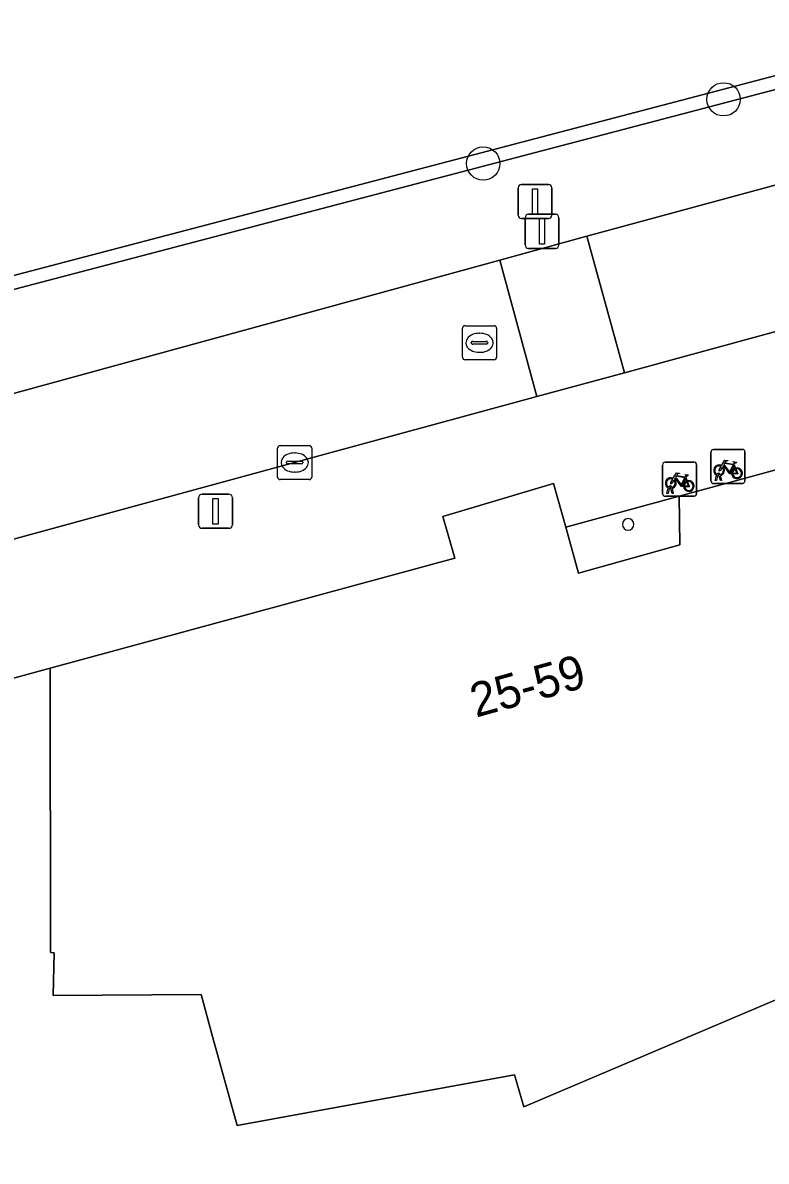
# Model space of a CAD drawing. Extents: x 159053 to 160042, y 380449 to 381423.
# Drawn here: x 159364.14 to 159385.97, y 380824.74 to 380858.17 of the extents above; entities that cross this region are included whole.
import ezdxf

# ---------------------------------------------------------------- set-up
doc = ezdxf.new("R2010")
doc.units = 0
for name, color, linetype in [('IMGEO_Afsluitpaal', 7, 'Continuous'), ('IMGEO_Boom', 7, 'Continuous'), ('IMGEO_Erf', 7, 'Continuous'), ('IMGEO_Fietsenrek', 7, 'Continuous'), ('IMGEO_Groenvoorziening', 7, 'Continuous'), ('IMGEO_Haag', 7, 'Continuous'), ('IMGEO_Kolk', 7, 'Continuous'), ('IMGEO_Lichtmast', 7, 'Continuous'), ('IMGEO_Pand', 7, 'Continuous'), ('IMGEO_Pand_nummerreeks', 7, 'Continuous'), ('IMGEO_Rijbaan_lokaal_open', 7, 'Continuous'), ('IMGEO_Rioolput', 7, 'Continuous'), ('IMGEO_Voetpad_open', 7, 'Continuous')]:
    doc.layers.add(name, color=color, linetype=linetype)

msp = doc.modelspace()

# ---------------------------------------------------------------- linework, layer by layer
at = {"layer": 'IMGEO_Afsluitpaal'}
for p, q in [((159378.684, 380852.517), (159378.684, 380853.317)), ((159378.684, 380853.317), (159378.684, 380852.517)), ((159378.784, 380853.417), (159379.574, 380853.417)), ((159379.574, 380853.417), (159378.784, 380853.417)), ((159379.674, 380853.317), (159379.674, 380852.517)), ((159379.674, 380852.517), (159379.674, 380853.317)), ((159379.574, 380852.417), (159378.784, 380852.417)), ((159378.784, 380852.417), (159379.574, 380852.417)), ((159378.886, 380851.643), (159378.886, 380852.443)), ((159378.886, 380852.443), (159378.886, 380851.643)), ((159378.986, 380852.543), (159379.776, 380852.543)), ((159379.776, 380852.543), (159378.986, 380852.543)), ((159379.876, 380852.443), (159379.876, 380851.643)), ((159379.876, 380851.643), (159379.876, 380852.443)), ((159379.776, 380851.543), (159378.986, 380851.543)), ((159378.986, 380851.543), (159379.776, 380851.543))]:
    msp.add_line(p, q, dxfattribs=at)
for points in [[(159379.104, 380853.292), (159379.254, 380853.292), (159379.254, 380852.542), (159379.104, 380852.542), (159379.104, 380853.292)], [(159379.306, 380852.418), (159379.456, 380852.418), (159379.456, 380851.668), (159379.306, 380851.668), (159379.306, 380852.418)]]:
    msp.add_lwpolyline(points, dxfattribs=at)
for centre, start, end in [((159378.784, 380853.317), 90, 180), ((159378.784, 380853.317), 90, 180), ((159379.574, 380853.317), 0, 90), ((159379.574, 380853.317), 360, 90), ((159378.784, 380852.517), 180, 270), ((159378.784, 380852.517), 180, 270), ((159378.986, 380852.443), 90, 180), ((159378.986, 380852.443), 90, 180), ((159379.574, 380852.517), 270, 0), ((159379.574, 380852.517), 270, 0), ((159379.776, 380852.443), 0, 90), ((159379.776, 380852.443), 360, 90), ((159378.986, 380851.643), 180, 270), ((159378.986, 380851.643), 180, 270), ((159379.776, 380851.643), 270, 0), ((159379.776, 380851.643), 270, 0)]:
    msp.add_arc(centre, 0.1, start, end, dxfattribs=at)
at = {"layer": 'IMGEO_Boom'}
for centre in [(159384.716, 380855.918), (159377.659, 380854.033)]:
    msp.add_circle(centre, 0.489, dxfattribs=at)
at = {"layer": 'IMGEO_Erf'}
msp.add_lwpolyline([(159389.815, 380824.538), (159402.333, 380832.35), (159393.73, 380847.1), (159391.961, 380846.597), (159396.172, 380839.392), (159396.866, 380838.211), (159393.026, 380835.951), (159393.845, 380832.956), (159388.154, 380828.951), (159387.813, 380830.148), (159378.848, 380826.342), (159378.573, 380827.282), (159370.429, 380825.789), (159369.712, 380828.402), (159369.374, 380829.635), (159365.031, 380829.603), (159365.059, 380830.863), (159364.954, 380830.868), (159364.937, 380839.219), (159363.135, 380838.73)], dxfattribs=at)
msp.add_lwpolyline([(159380.08, 380843.353), (159380.457, 380842.006), (159383.434, 380842.835), (159383.414, 380844.263)], close=True, dxfattribs=at)
for start, end in [(0, 180), (180, 0)]:
    msp.add_arc((159381.914, 380843.44), 0.17, start, end, dxfattribs=at)
at = {"layer": 'IMGEO_Fietsenrek'}
for p, q in [((159384.417, 380845.639), (159385.258, 380845.639)), ((159385.258, 380845.639), (159384.417, 380845.639)), ((159382.999, 380845.265), (159383.84, 380845.265)), ((159383.84, 380845.265), (159382.999, 380845.265)), ((159384.342, 380844.714), (159384.342, 380845.555)), ((159384.342, 380845.555), (159384.342, 380844.714)), ((159385.342, 380845.564), (159385.342, 380844.723)), ((159385.342, 380844.723), (159385.342, 380845.564)), ((159382.924, 380844.34), (159382.924, 380845.181)), ((159382.924, 380845.181), (159382.924, 380844.34)), ((159383.924, 380845.19), (159383.924, 380844.349)), ((159383.924, 380844.349), (159383.924, 380845.19)), ((159385.029, 380845.188), (159385.065, 380845.093)), ((159383.611, 380844.814), (159383.647, 380844.719)), ((159385.267, 380844.639), (159384.426, 380844.639)), ((159384.426, 380844.639), (159385.267, 380844.639)), ((159384.469, 380844.723), (159384.508, 380844.883)), ((159384.503, 380844.723), (159384.469, 380844.723)), ((159384.538, 380844.871), (159384.503, 380844.723)), ((159384.58, 380844.895), (159384.579, 380844.899)), ((159384.621, 380844.723), (159384.587, 380844.865)), ((159384.611, 380844.906), (159384.612, 380844.899)), ((159384.619, 380844.869), (159384.654, 380844.723)), ((159384.654, 380844.723), (159384.621, 380844.723)), ((159383.849, 380844.265), (159383.008, 380844.265)), ((159383.008, 380844.265), (159383.849, 380844.265)), ((159383.051, 380844.349), (159383.09, 380844.509)), ((159383.085, 380844.349), (159383.051, 380844.349)), ((159383.12, 380844.497), (159383.085, 380844.349)), ((159383.162, 380844.521), (159383.161, 380844.525)), ((159383.203, 380844.349), (159383.169, 380844.491)), ((159383.193, 380844.532), (159383.194, 380844.525)), ((159383.201, 380844.495), (159383.236, 380844.349)), ((159383.236, 380844.349), (159383.203, 380844.349))]:
    msp.add_line(p, q, dxfattribs=at)
for points in [[(159384.655, 380845.165), (159384.75, 380845.329), (159384.836, 380845.315), (159384.838, 380845.306), (159384.782, 380845.295), (159384.755, 380845.25), (159385.011, 380845.209)], [(159385.011, 380845.209), (159385.036, 380845.258), (159385.03, 380845.262), (159385.007, 380845.266), (159384.995, 380845.273), (159384.994, 380845.276), (159384.996, 380845.281), (159385.091, 380845.266), (159385.093, 380845.256), (159385.083, 380845.243), (159385.071, 380845.237), (159385.057, 380845.243), (159385.029, 380845.188)], [(159383.237, 380844.791), (159383.332, 380844.955), (159383.418, 380844.941), (159383.42, 380844.932), (159383.364, 380844.921), (159383.337, 380844.876), (159383.593, 380844.835)], [(159384.676, 380845.113), (159384.624, 380845.023), (159384.584, 380844.998), (159384.585, 380845.045), (159384.64, 380845.139)], [(159384.951, 380844.921), (159384.901, 380844.921), (159384.71, 380845.172), (159384.691, 380845.14)], [(159384.998, 380845.184), (159384.741, 380845.225), (159384.724, 380845.196), (159384.891, 380844.976), (159384.998, 380845.184)], [(159385.046, 380845.086), (159385.016, 380845.163), (159384.907, 380844.945), (159384.95, 380844.945)], [(159384.98, 380844.945), (159385.1, 380844.944), (159385.056, 380845.058)], [(159385.076, 380845.065), (159385.131, 380844.92), (159384.981, 380844.92)], [(159383.258, 380844.739), (159383.206, 380844.649), (159383.166, 380844.624), (159383.167, 380844.671), (159383.222, 380844.765)], [(159383.533, 380844.547), (159383.483, 380844.547), (159383.292, 380844.798), (159383.273, 380844.766)], [(159383.58, 380844.81), (159383.323, 380844.851), (159383.306, 380844.822), (159383.473, 380844.602), (159383.58, 380844.81)], [(159383.628, 380844.712), (159383.598, 380844.789), (159383.489, 380844.571), (159383.532, 380844.571)], [(159383.562, 380844.571), (159383.682, 380844.57), (159383.638, 380844.684)], [(159383.658, 380844.691), (159383.713, 380844.546), (159383.563, 380844.546)], [(159383.593, 380844.835), (159383.618, 380844.884), (159383.612, 380844.888), (159383.589, 380844.892), (159383.577, 380844.899), (159383.576, 380844.902), (159383.578, 380844.907), (159383.673, 380844.892), (159383.675, 380844.882), (159383.665, 380844.869), (159383.653, 380844.863), (159383.639, 380844.869), (159383.611, 380844.814)]]:
    msp.add_lwpolyline(points, dxfattribs=at)
for centre, radius, start, end in [((159384.42, 380845.561), 0.0779, 92.4484, 184.2845), ((159384.42, 380845.561), 0.0779, 92.4484, 184.2845), ((159385.264, 380845.561), 0.0779, 2.4484, 94.2845), ((159385.264, 380845.561), 0.0779, 2.4484, 94.2845), ((159383.002, 380845.187), 0.0779, 92.4484, 184.2845), ((159383.002, 380845.187), 0.0779, 92.4484, 184.2845), ((159383.846, 380845.187), 0.0779, 2.4484, 94.2845), ((159383.846, 380845.187), 0.0779, 2.4484, 94.2845), ((159384.582, 380845.024), 0.159, 62.6766, 242.1369), ((159384.582, 380845.024), 0.129, 63.3192, 238.903), ((159384.562, 380844.895), 0.0499, 12.8025, 158.6934), ((159384.582, 380845.024), 0.129, 283.6043, 43.4302), ((159384.582, 380845.024), 0.159, 283.5766, 46.6042), ((159385.109, 380844.94), 0.159, 113.3408, 178.3217), ((159385.109, 380844.94), 0.159, 187.0065, 105.7708), ((159385.109, 380844.94), 0.129, 113.923, 177.9556), ((159385.109, 380844.94), 0.129, 188.6715, 104.5883), ((159383.164, 380844.65), 0.159, 62.6766, 242.1369), ((159383.164, 380844.65), 0.129, 63.3192, 238.903), ((159383.164, 380844.65), 0.129, 283.6043, 43.4302), ((159383.164, 380844.65), 0.159, 283.5766, 46.6042), ((159383.691, 380844.566), 0.159, 113.3408, 178.3217), ((159383.691, 380844.566), 0.159, 187.0065, 105.7708), ((159383.691, 380844.566), 0.129, 113.923, 177.9556), ((159383.691, 380844.566), 0.129, 188.6715, 104.5883), ((159384.42, 380844.717), 0.0779, 182.4484, 274.2845), ((159384.42, 380844.717), 0.0779, 182.4484, 274.2845), ((159384.582, 380845.024), 0.159, 253.9967, 271.7867), ((159384.562, 380844.895), 0.0174, 12.8025, 163.4502), ((159384.582, 380845.024), 0.129, 253.415, 269.0204), ((159385.264, 380844.717), 0.0779, 272.4484, 4.2845), ((159385.264, 380844.717), 0.0779, 272.4484, 4.2845), ((159383.002, 380844.343), 0.0779, 182.4484, 274.2845), ((159383.002, 380844.343), 0.0779, 182.4484, 274.2845), ((159383.144, 380844.521), 0.0499, 12.8025, 158.6934), ((159383.164, 380844.65), 0.159, 253.9967, 271.7867), ((159383.144, 380844.521), 0.0174, 12.8025, 163.4502), ((159383.164, 380844.65), 0.129, 253.415, 269.0204), ((159383.846, 380844.343), 0.0779, 272.4484, 4.2845), ((159383.846, 380844.343), 0.0779, 272.4484, 4.2845)]:
    msp.add_arc(centre, radius, start, end, dxfattribs=at)
at = {"layer": 'IMGEO_Groenvoorziening'}
for points in [[(159339.63, 380858.444), (159343.386, 380845.223), (159357.481, 380849.075), (159416.608, 380864.597), (159415.898, 380867.448), (159412.172, 380882.306), (159399.303, 380929.877)], [(159378.145, 380851.195), (159380.699, 380851.901), (159412.443, 380860.514), (159415.366, 380861.29), (159417.874, 380861.883), (159417.452, 380863.784), (159416.656, 380864.403), (159416.707, 380864.21), (159357.585, 380848.689), (159343.492, 380844.837), (159340.652, 380844.061), (159220.908, 380811.334), (159220.855, 380811.527), (159220.802, 380811.72), (159194.979, 380906.143), (159194.248, 380908.271), (159191.665, 380904.574), (159202.148, 380866.415), (159202.911, 380863.663), (159207.936, 380845.286), (159216.661, 380813.316)], [(159224.154, 380809.069), (159238.334, 380812.95), (159237.679, 380815.383), (159241.802, 380816.509), (159242.456, 380814.078), (159262.189, 380819.479), (159264.76, 380820.184), (159291.981, 380827.607), (159291.367, 380829.924), (159295.75, 380831.125), (159296.393, 380828.81), (159310.422, 380832.636), (159318.548, 380834.869), (159321.098, 380835.572), (159350.091, 380843.512), (159349.447, 380845.979), (159353.576, 380847.071), (159354.213, 380844.641), (159378.145, 380851.195)]]:
    msp.add_lwpolyline(points, dxfattribs=at)
msp.add_lwpolyline([(159416.656, 380864.403), (159416.608, 380864.597), (159357.481, 380849.075), (159343.386, 380845.223), (159340.546, 380844.447), (159220.802, 380811.72), (159220.855, 380811.527), (159220.908, 380811.334), (159340.652, 380844.061), (159343.492, 380844.837), (159357.585, 380848.689), (159416.707, 380864.21)], close=True, dxfattribs=at)
at = {"layer": 'IMGEO_Haag'}
msp.add_lwpolyline([(159416.656, 380864.403), (159416.608, 380864.597), (159357.481, 380849.075), (159343.386, 380845.223), (159340.546, 380844.447), (159220.802, 380811.72), (159220.855, 380811.527), (159220.908, 380811.334), (159340.652, 380844.061), (159343.492, 380844.837), (159357.585, 380848.689), (159416.707, 380864.21)], close=True, dxfattribs=at)
at = {"layer": 'IMGEO_Kolk'}
for p, q in [((159371.62, 380844.829), (159371.62, 380845.681)), ((159371.695, 380845.755), (159372.547, 380845.755)), ((159372.621, 380845.681), (159372.621, 380844.829)), ((159371.879, 380845.249), (159371.879, 380845.261)), ((159371.922, 380845.298), (159372.32, 380845.298)), ((159372.108, 380845.535), (159372.133, 380845.535)), ((159372.363, 380845.261), (159372.363, 380845.249)), ((159372.317, 380845.212), (159371.919, 380845.212)), ((159372.131, 380844.975), (159372.106, 380844.975)), ((159372.547, 380844.755), (159371.695, 380844.755))]:
    msp.add_line(p, q, dxfattribs=at)
for points in [[(159371.62, 380844.829), (159371.62, 380845.681)], [(159371.695, 380845.755), (159372.547, 380845.755)], [(159372.621, 380845.681), (159372.621, 380844.829)], [(159372.547, 380844.755), (159371.695, 380844.755)]]:
    msp.add_lwpolyline(points, dxfattribs=at)
for centre, radius, start, end in [((159371.697, 380845.679), 0.0765, 91.552, 178.448), ((159371.697, 380845.679), 0.0765, 91.552, 178.448), ((159372.545, 380845.679), 0.0765, 1.552, 88.448), ((159372.545, 380845.679), 0.0765, 1.552, 88.448), ((159371.919, 380845.258), 0.0403, 85.8775, 175.7526), ((159372.324, 380845.26), 0.0386, 1.7309, 96.639), ((159371.916, 380845.248), 0.0366, 178.938, 274.7102), ((159372.32, 380845.255), 0.043, 264.8664, 352.4533), ((159371.697, 380844.831), 0.0765, 181.552, 268.448), ((159371.697, 380844.831), 0.0765, 181.552, 268.448), ((159372.545, 380844.831), 0.0765, 271.552, 358.448), ((159372.545, 380844.831), 0.0765, 271.552, 358.448)]:
    msp.add_arc(centre, radius, start, end, dxfattribs=at)
for centre, major_axis, ratio, start_param, end_param in [((159372.107, 380845.255), (-0.387, 0.002), 0.722429, 4.712389, 7.853982), ((159372.132, 380845.255), (-0.39, 0.002), 0.717154, 1.570796, 4.712389)]:
    msp.add_ellipse(centre, major_axis=major_axis, ratio=ratio, start_param=start_param, end_param=end_param, dxfattribs=at)
at = {"layer": 'IMGEO_Lichtmast'}
for p, q in [((159369.4, 380844.323), (159370.19, 380844.323)), ((159370.19, 380844.323), (159369.4, 380844.323)), ((159369.3, 380843.423), (159369.3, 380844.223)), ((159369.3, 380844.223), (159369.3, 380843.423)), ((159370.29, 380844.223), (159370.29, 380843.423)), ((159370.29, 380843.423), (159370.29, 380844.223)), ((159370.19, 380843.323), (159369.4, 380843.323)), ((159369.4, 380843.323), (159370.19, 380843.323))]:
    msp.add_line(p, q, dxfattribs=at)
msp.add_lwpolyline([(159369.72, 380844.198), (159369.87, 380844.198), (159369.87, 380843.448), (159369.72, 380843.448), (159369.72, 380844.198)], dxfattribs=at)
for centre, start, end in [((159369.4, 380844.223), 90, 180), ((159369.4, 380844.223), 90, 180), ((159370.19, 380844.223), 0, 90), ((159370.19, 380844.223), 360, 90), ((159369.4, 380843.423), 180, 270), ((159369.4, 380843.423), 180, 270), ((159370.19, 380843.423), 270, 0), ((159370.19, 380843.423), 270, 0)]:
    msp.add_arc(centre, 0.1, start, end, dxfattribs=at)
at = {"layer": 'IMGEO_Pand'}
msp.add_lwpolyline([(159391.961, 380846.597), (159383.414, 380844.263), (159383.434, 380842.835), (159380.457, 380842.006), (159380.08, 380843.353), (159379.724, 380844.635), (159376.47, 380843.674), (159376.821, 380842.444), (159364.937, 380839.219), (159364.954, 380830.868), (159365.059, 380830.863), (159365.031, 380829.603), (159369.374, 380829.635), (159369.712, 380828.402), (159370.429, 380825.789), (159378.573, 380827.282), (159378.848, 380826.342), (159387.813, 380830.148), (159388.154, 380828.951), (159393.845, 380832.956), (159393.026, 380835.951), (159396.866, 380838.211), (159396.172, 380839.392)], close=True, dxfattribs=at)
for start, end in [(0, 180), (180, 0)]:
    msp.add_arc((159381.914, 380843.44), 0.17, start, end, dxfattribs=at)
at = {"layer": 'IMGEO_Rijbaan_lokaal_open'}
msp.add_lwpolyline([(159429.314, 380864.482), (159420.414, 380862.437), (159419.224, 380862.163), (159417.874, 380861.883), (159415.366, 380861.29), (159412.443, 380860.514), (159380.699, 380851.901), (159381.803, 380847.893), (159390.372, 380850.232), (159405.799, 380854.42)], dxfattribs=at)
for points in [[(159380.699, 380851.901), (159378.145, 380851.195), (159379.234, 380847.194), (159381.803, 380847.893)], [(159350.091, 380843.512), (159321.098, 380835.572), (159322.165, 380831.571), (159332.681, 380834.468), (159359.226, 380841.739), (159372.116, 380845.256), (159379.234, 380847.194), (159378.145, 380851.195), (159354.213, 380844.641)]]:
    msp.add_lwpolyline(points, close=True, dxfattribs=at)
at = {"layer": 'IMGEO_Rioolput'}
for p, q in [((159377.123, 380849.27), (159377.975, 380849.27)), ((159377.048, 380848.344), (159377.048, 380849.196)), ((159377.536, 380849.05), (159377.561, 380849.05)), ((159378.049, 380849.196), (159378.049, 380848.344)), ((159377.307, 380848.764), (159377.307, 380848.776)), ((159377.745, 380848.727), (159377.347, 380848.727)), ((159377.35, 380848.813), (159377.748, 380848.813)), ((159377.791, 380848.776), (159377.791, 380848.764)), ((159377.975, 380848.27), (159377.123, 380848.27)), ((159377.559, 380848.49), (159377.534, 380848.49))]:
    msp.add_line(p, q, dxfattribs=at)
for points in [[(159377.123, 380849.27), (159377.975, 380849.27)], [(159377.048, 380848.344), (159377.048, 380849.196)], [(159378.049, 380849.196), (159378.049, 380848.344)], [(159377.975, 380848.27), (159377.123, 380848.27)]]:
    msp.add_lwpolyline(points, dxfattribs=at)
for centre, radius, start, end in [((159377.125, 380849.194), 0.0765, 91.552, 178.448), ((159377.125, 380849.194), 0.0765, 91.552, 178.448), ((159377.973, 380849.194), 0.0765, 1.552, 88.448), ((159377.973, 380849.194), 0.0765, 1.552, 88.448), ((159377.347, 380848.773), 0.0403, 85.8775, 175.7526), ((159377.344, 380848.763), 0.0366, 178.938, 274.7102), ((159377.748, 380848.77), 0.043, 264.8664, 352.4533), ((159377.752, 380848.775), 0.0386, 1.7309, 96.639), ((159377.125, 380848.346), 0.0765, 181.552, 268.448), ((159377.125, 380848.346), 0.0765, 181.552, 268.448), ((159377.973, 380848.346), 0.0765, 271.552, 358.448), ((159377.973, 380848.346), 0.0765, 271.552, 358.448)]:
    msp.add_arc(centre, radius, start, end, dxfattribs=at)
for centre, major_axis, ratio, start_param, end_param in [((159377.535, 380848.77), (-0.387, 0.002), 0.722429, 4.712389, 7.853982), ((159377.56, 380848.77), (-0.39, 0.002), 0.717154, 1.570796, 4.712389)]:
    msp.add_ellipse(centre, major_axis=major_axis, ratio=ratio, start_param=start_param, end_param=end_param, dxfattribs=at)
at = {"layer": 'IMGEO_Voetpad_open'}
for points in [[(159405.799, 380854.42), (159390.372, 380850.232), (159381.803, 380847.893), (159379.234, 380847.194), (159372.116, 380845.256), (159359.226, 380841.739), (159332.681, 380834.468), (159322.165, 380831.571), (159319.62, 380830.875), (159311.901, 380828.765), (159287.285, 380822.066), (159272.965, 380818.161), (159265.828, 380816.188), (159263.275, 380815.492), (159254.307, 380813.067), (159229.759, 380806.373), (159225.787, 380805.28)], [(159363.132, 380839.444), (159363.135, 380838.73), (159364.937, 380839.219), (159376.821, 380842.444), (159376.47, 380843.674), (159379.724, 380844.635), (159380.08, 380843.353), (159383.414, 380844.263), (159391.961, 380846.597), (159393.73, 380847.1), (159393.413, 380847.649)]]:
    msp.add_lwpolyline(points, dxfattribs=at)

# ---------------------------------------------------------------- texts
at = {"layer": 'IMGEO_Pand_nummerreeks'}
msp.add_text('25-59', height=1, rotation=15.5608, dxfattribs=at).set_placement((159377.441, 380837.762))

doc.saveas('drawing.dxf')
